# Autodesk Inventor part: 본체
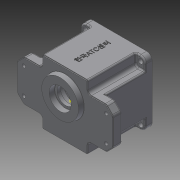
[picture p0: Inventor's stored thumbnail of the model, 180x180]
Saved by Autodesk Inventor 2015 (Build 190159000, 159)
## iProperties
Created: 2016-02
Part Number: 본체
Material: Generic
Document SubType Name: Modeling
Designer: Administrator
Density: 1 g/cm^3
Appearance: Default
Author: Administrator
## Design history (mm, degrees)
sketch "Sketch1"
  geometry: L1 (47, -47)-(-47, -47); L2 (-47, -47)-(-47, 47); L3 (-47, 47)-(47, 47); L4 (47, 47)-(47, -47); L5 (47, -47)-(-47, 47); L6 (-47, -47)-(47, 47); 1 further point
  constraints: 12 end point, 2 midpoint, 2 parallel, 1 horizontal, 1 perpendicular
  dimensions: "d0" = 94 distance of L2.end L3.end; "d1" = 94 distance of L1.end L2.end
extrude "Extrusion1" new body sketch "Sketch1" distance "d2" = 10; taper "d3" = 0 deg
workplane "Work Plane1"
sketch "Sketch2"
  geometry: L1 (33, -47)-(-33, -47); L2 (-33, 47)-(33, 47); L3 (33, -47)-(-33, 47); L4 (-33, -47)-(33, 47); L5 (-70, 30)-(-70, -30); L6 (70, -30)-(70, 30); L7 (70, 30)-(33, 30); L8 (-33, 30)-(-70, 30); L9 (-70, -30)-(-33, -30); L10 (33, -30)-(70, -30); L11 (33, 47)-(33, 30); L12 (33, -30)-(33, -47); L13 (-33, -47)-(-33, -30); L14 (-33, 30)-(-33, 47); 1 further point
  constraints: 28 end point, 10 parallel, 4 perpendicular, 3 horizontal, 2 midpoint
  dimensions: "d5" = 94 distance of L1.end L2.start; "d6" = 66 distance of L2.start L2.end; "d8" = 140 distance of L6.end L5.start; "d9" = 70 distance from line of L5 point (0, 0); "d10" = 60 distance of L5.start L5.end
extrude "Extrusion2" join sketch "Sketch2" distance "d12" = 13; taper "d13" = 0 deg
workplane "Work Plane2"
sketch "Sketch3"
  geometry: L1 (47, -47)-(-47, -47) reference; L2 (-47, -47)-(-47, 47) reference; L3 (-47, 47)-(47, 47) reference; L4 (47, 47)-(47, -47) reference; L5 (-33, 30)-(-33, 47) reference; L6 (-47, 47)-(-33, 47); L7 (-33, 47)-(-33, 30); L8 (-33, 30)-(-47, 30); L9 (-47, 30)-(-47, 47); L10 (-47, -47)-(-33, -47); L11 (-33, -47)-(-33, -30); L12 (-33, -30)-(-47, -30); L13 (-47, -30)-(-47, -47); L14 (47, -47)-(33, -47); L15 (33, -47)-(33, -30); L16 (33, -30)-(47, -30); L17 (47, -30)-(47, -47); L18 (47, 47)-(33, 47); L19 (33, 47)-(33, 30); L20 (33, 30)-(47, 30); L21 (47, 30)-(47, 47); 1 further point
  constraints: 32 end point, 8 parallel, 4 horizontal, 4 perpendicular
extrude "Extrusion3" join sketch "Sketch3" stored distance "d15" = 10; taper "d16" = 0 deg
sketch "Sketch4"
  geometry: L1 (47, 47)-(33, 47); L2 (33, 47)-(33, 30); L3 (33, 30)-(47, 30); L4 (47, 30)-(47, 47); L5 (47, -47)-(33, -47); L6 (33, -47)-(33, -30); L7 (33, -30)-(47, -30); L8 (47, -30)-(47, -47); L9 (-47, -47)-(-33, -47); L10 (-33, -47)-(-33, -30); L11 (-33, -30)-(-47, -30); L12 (-47, -30)-(-47, -47); L13 (-47, 47)-(-33, 47); L14 (-33, 47)-(-33, 30); L15 (-33, 30)-(-47, 30); L16 (-47, 30)-(-47, 47); 1 further point
  constraints: 32 end point, 8 parallel, 4 horizontal, 4 perpendicular
extrude "Extrusion4" cut sketch "Sketch4" distance "d17" = 60; taper "d18" = 0 deg
fillet "Fillet1" dims "d19" = 8
sketch "Sketch5"
  geometry: C1 r 43 at (0, 0); 1 further point
  constraints: 1 centre point, 1 coincident
  dimensions: "d20" = 43 radius of C1
extrude "Extrusion5" cut sketch "Sketch5" distance "d21" = 9; taper "d22" = 0 deg
sketch "Sketch6"
  geometry: A1 r 40 centre (0, 0) between (40, 0) and (39.148, 8.214); A2 r 36 centre (0, 0) between (36, 0) and (-36, 0); A3 r 4 centre (36, 0) between (35.852, 3.997) and (35.852, -3.997); A4 r 4 centre (-36, 0) between (-35.852, -3.997) and (-35.852, 3.997); A5 r 3.5 centre (35.722, -7.495) between (39.148, -8.214) and (35.778, -3.995); A6 r 3.5 centre (35.722, 7.495) between (35.778, 3.995) and (39.148, 8.214); A7 r 3.5 centre (-35.722, -7.495) between (-35.778, -3.995) and (-39.148, -8.214); A8 r 3.5 centre (-35.722, 7.495) between (-39.148, 8.214) and (-35.778, 3.995); A9 r 40 centre (0, 0) between (39.148, -8.214) and (40, 0); A10 r 40 centre (0, 0) between (39.148, 8.214) and (-39.148, 8.214); A11 r 4 centre (36, 0) between (40, 0) and (35.852, 3.997); A12 r 4 centre (36, 0) between (35.852, -3.997) and (40, 0); A13 r 4 centre (-36, 0) between (-40, 0) and (-35.852, -3.997); A14 r 4 centre (-36, 0) between (-35.852, 3.997) and (-40, 0); A15 r 40 centre (0, 0) between (-39.148, 8.214) and (-39.148, -8.214); A16 r 40 centre (0, 0) between (-39.148, -8.214) and (39.148, -8.214); 1 further point
  constraints: 46 point on circle, 16 centre point, 8 tangent, 2 coincident, 2 horizontal alignment
  dimensions: "d81" = 40 radius of A1; "d160" = 72 diameter of A2; "d161" = 4 radius of A3; "d162" = 4 radius of A4; "d163" = 3.5 radius of A7; "d164" = 3.5 radius of A8; "d165" = 3.5 radius of A5; "d166" = 3.5 radius of A6
extrude "Extrusion6" cut sketch "Sketch6" distance "d24" = 62; taper "d25" = 0 deg
sketch "Sketch8"
  geometry: C1 r 28 at (0, 11); 1 further point
  constraints: 1 centre point, 1 vertical alignment
  dimensions: "d32" = 28 radius of C1; "d33" = 11 distance of point (0, 0) C1.centre
extrude "Extrusion8" join sketch "Sketch8" distance "d34" = 7; taper "d35" = -10 deg
sketch "Sketch9"
  geometry: 1 further point
sketch "Sketch10"
  geometry: C1 r 21 at (0, -11); 1 further point
  constraints: 1 centre point, 1 vertical alignment
  dimensions: "d36" = 21 radius of C1; "d37" = 11 distance of point (0, 0) C1.centre
extrude "Extrusion9" join sketch "Sketch10" distance "d38" = 7; taper "d39" = 0 deg
sketch "Sketch12"
  geometry: C1 r 16 at (0, 0); C2 r 28 at (0, 0) reference; 1 further point
  constraints: 1 centre point, 1 concentric
  dimensions: "d43" = 16 radius of C1
extrude "Extrusion11" cut sketch "Sketch12" distance "d44" = 8; taper "d45" = 0 deg
sketch "Sketch13"
  geometry: C1 r 15 at (0, 20); 1 further point
  constraints: 1 centre point, 1 vertical alignment
  dimensions: "d46" = 15 radius of C1; "d47" = 20 distance of point (0, 0) C1.centre
extrude "Extrusion12" join sketch "Sketch13" distance "d48" = 7; taper "d49" = 0 deg
sketch "Sketch14"
  geometry: C1 r 11 at (0, 20); A1 r 15 centre (0, 20) between (8.978, 7.984) and (-8.978, 7.984) reference; 1 further point
  constraints: 1 centre point, 1 coincident, 1 vertical alignment
  dimensions: "d50" = 11 radius of C1
extrude "Extrusion13" cut sketch "Sketch14" distance "d51" = 7; taper "d52" = 0 deg
sketch "Sketch15"
  geometry: C1 r 9.5 at (0, 0); C2 r 11 at (0, 0) reference; 1 further point
  constraints: 1 centre point, 1 concentric
  dimensions: "d53" = 9.5 radius of C1
extrude "Extrusion14" cut sketch "Sketch15" distance "d54" = 1; taper "d55" = 0 deg
chamfer "Chamfer1" distance "d56" = 10; stored, may be unused: second distance "d57" = 2, angle "d58" = 45 deg
fillet "Fillet2" dims "d62" = 2
fillet "Fillet4" dims "d64" = 2
fillet "Fillet5" dims "d65" = 3
sketch "Sketch18"
  geometry: L1 (40, 40)-(-40, 40); L2 (-40, 40)-(-40, -40); L3 (-40, -40)-(40, -40); L4 (40, -40)-(40, 40); L5 (40, 40)-(-40, -40); L6 (-40, 40)-(40, -40); 5 further points
  constraints: 12 end point, 4 coincident, 2 midpoint, 2 parallel, 1 horizontal, 1 perpendicular
  dimensions: "d91" = 80 distance of L3.end L2.end; "d92" = 80 distance of L2.end L1.end
hole "Hole1" sketch "Sketch18" at (40, -40), (-40, -40), (-40, 40), (40, 40) diameter "d93" = 7; stored, may be unused: countersink angle "d97" = 90 deg, drill point angle "d99" = 118 deg; dims "d94" = 6, "d95" = 4, "d96" = 2, "d98" = 8
fillet "Fillet7" dims "d100" = 3
sketch "Sketch19"
  geometry: L1 (-60, -19)-(60, -19); L2 (60, -19)-(60, 19); L3 (60, 19)-(-60, 19); L4 (-60, 19)-(-60, -19); L5 (-60, -19)-(60, 19); L6 (60, -19)-(-60, 19); 5 further points
  constraints: 12 end point, 4 coincident, 2 midpoint, 2 parallel, 1 horizontal, 1 perpendicular
  dimensions: "d101" = 120 distance of L3.end L2.end; "d102" = 38 distance of L2.end L1.end
sketch "Sketch20"
  geometry: L1 (-60, 19)-(60, 19) reference; L2 (-60, -19)-(-60, 19) reference; L3 (60, -19)-(-60, -19) reference; L4 (60, 19)-(60, -19) reference; 5 further points
  constraints: 4 coincident
hole "Hole2" sketch "Sketch20" at (-60, 19), (60, 19), (60, -19), (-60, -19) diameter "d103" = 5; stored, may be unused: countersink angle "d107" = 90 deg, drill point angle "d109" = 118 deg; dims "d104" = 6, "d105" = 9, "d106" = 4, "d108" = 8
chamfer "Chamfer3" distance "d115" = 1; stored, may be unused: second distance "d116" = 2, angle "d117" = 45 deg
fillet "Fillet8" dims "d121" = 0.3
fillet "Fillet9" dims "d122" = 1
sketch "Sketch25"
  geometry: L1 (0, 0)-(78, 0) reference; L2 (39, 16)-(39, -96) reference; 2 further points
  constraints: 1 midpoint, 1 other
  dimensions: "d123" = 40 distance from line of L1 point (39, -40)
emboss "Emboss1" sketch "Sketch25" dims "d124" = 0.5, "d125" = 0
fillet "Fillet12" dims "d128" = 5
fillet "Fillet13" dims "d129" = 5
fillet "Fillet14" dims "d130" = 2
fillet "Fillet15" dims "d131" = 2
sketch "Sketch26"
  geometry: C1 r 17.5 at (0, -11); A1 r 21 centre (0, -11) between (-12.163, 6.119) and (12.163, 6.119) reference; 1 further point
  constraints: 1 centre point, 1 concentric
  dimensions: "d132" = 17.5 radius of C1
extrude "Extrusion20" cut sketch "Sketch26" distance "d133" = 10; taper "d134" = 0 deg
sketch "Sketch27"
  geometry: C1 r 12.5 at (0, 0); C2 r 17.5 at (0, 0) reference; 1 further point
  constraints: 1 centre point, 1 concentric
  dimensions: "d135" = 12.5 radius of C1
extrude "Extrusion21" cut sketch "Sketch27" distance "d136" = 5; taper "d137" = 0 deg
fillet "Fillet16" dims "d138" = 0.3
chamfer "Chamfer4" distance "d139" = 1; stored, may be unused: second distance "d140" = 2, angle "d141" = 45 deg
fillet "Fillet19" dims "d145" = 2
sketch "Sketch30"
  geometry: L1 (-33, 45)-(-33, 35) reference; L2 (-38, 30)-(-57.929, 30) reference; L3 (-68.536, 21.464)-(-61.464, 28.536) reference; L4 (-70, 17.929)-(-70, -17.929) reference; L5 (-61.464, -28.536)-(-68.536, -21.464) reference; L6 (-57.929, -30)-(-38, -30) reference; L7 (-33, -35)-(-33, -45) reference; L8 (-31, -47)-(31, -47) reference; L9 (33, -45)-(33, -35) reference; L10 (38, -30)-(57.929, -30) reference; L11 (68.536, -21.464)-(61.464, -28.536) reference; L12 (70, -17.929)-(70, 17.929) reference; L13 (61.464, 28.536)-(68.536, 21.464) reference; L14 (57.929, 30)-(38, 30) reference; L15 (33, 35)-(33, 45) reference; L16 (31, 47)-(-31, 47) reference; L17 (-32, 45)-(-32, 35); L18 (-38, 29)-(-57.929, 29); L19 (-60.757, 27.828)-(-67.828, 20.757); L20 (-69, 17.929)-(-69, -17.929); L21 (-67.828, -20.757)-(-60.757, -27.828); L22 (-57.929, -29)-(-38, -29); L23 (-32, -35)-(-32, -45); L24 (-31, -46)-(31, -46); L25 (32, -45)-(32, -35); L26 (38, -29)-(57.929, -29); L27 (60.757, -27.828)-(67.828, -20.757); L28 (69, -17.929)-(69, 17.929); L29 (67.828, 20.757)-(60.757, 27.828); L30 (57.929, 29)-(38, 29); L31 (32, 35)-(32, 45); L32 (31, 46)-(-31, 46); C1 r 2.5 at (60, 19) reference; C2 r 2.5 at (-60, -19) reference; C3 r 2.5 at (60, -19) reference; C4 r 2.5 at (-60, 19) reference; C5 r 28 at (0, 11) reference; A1 r 2 centre (-31, 45) between (-31, 47) and (-33, 45) reference; A2 r 5 centre (-38, 35) between (-38, 30) and (-33, 35) reference; A3 r 5 centre (-57.929, 25) between (-57.929, 30) and (-61.464, 28.536) reference; A4 r 5 centre (-65, 17.929) between (-68.536, 21.464) and (-70, 17.929) reference; A5 r 5 centre (-65, -17.929) between (-70, -17.929) and (-68.536, -21.464) reference; A6 r 5 centre (-57.929, -25) between (-61.464, -28.536) and (-57.929, -30) reference; A7 r 5 centre (-38, -35) between (-33, -35) and (-38, -30) reference; A8 r 2 centre (-31, -45) between (-33, -45) and (-31, -47) reference; A9 r 2 centre (31, -45) between (31, -47) and (33, -45) reference; A10 r 5 centre (38, -35) between (38, -30) and (33, -35) reference; A11 r 5 centre (57.929, -25) between (57.929, -30) and (61.464, -28.536) reference; A12 r 5 centre (65, -17.929) between (68.536, -21.464) and (70, -17.929) reference; A13 r 5 centre (65, 17.929) between (70, 17.929) and (68.536, 21.464) reference; A14 r 5 centre (57.929, 25) between (61.464, 28.536) and (57.929, 30) reference; A15 r 5 centre (38, 35) between (33, 35) and (38, 30) reference; A16 r 2 centre (31, 45) between (33, 45) and (31, 47) reference; A17 r 1 centre (-31, 45) between (-31, 46) and (-32, 45); A18 r 6 centre (-38, 35) between (-38, 29) and (-32, 35); A19 r 4 centre (-57.929, 25) between (-57.929, 29) and (-60.757, 27.828); A20 r 4 centre (-65, 17.929) between (-67.828, 20.757) and (-69, 17.929); A21 r 4 centre (-65, -17.929) between (-69, -17.929) and (-67.828, -20.757); A22 r 4 centre (-57.929, -25) between (-60.757, -27.828) and (-57.929, -29); A23 r 6 centre (-38, -35) between (-32, -35) and (-38, -29); A24 r 1 centre (-31, -45) between (-32, -45) and (-31, -46); A25 r 1 centre (31, -45) between (31, -46) and (32, -45); A26 r 6 centre (38, -35) between (38, -29) and (32, -35); A27 r 4 centre (57.929, -25) between (57.929, -29) and (60.757, -27.828); A28 r 4 centre (65, -17.929) between (67.828, -20.757) and (69, -17.929); A29 r 4 centre (65, 17.929) between (69, 17.929) and (67.828, 20.757); A30 r 4 centre (57.929, 25) between (60.757, 27.828) and (57.929, 29); A31 r 6 centre (38, 35) between (32, 35) and (38, 29); A32 r 1 centre (31, 45) between (32, 45) and (31, 46); 1 further point
  constraints: 32 end point, 32 point on circle, 16 centre point, 31 other
  dimensions: "d146" = 1 distance between parallel lines of L16 L32
extrude "Extrusion22" cut sketch "Sketch30" distance "d147" = 1; taper "d148" = 0 deg
fillet "Fillet20" dims "d167" = 2
sketch "Sketch32"
  geometry: A1 r 4 centre (36, 0) between (35.852, 3.997) and (35.852, -3.997) reference; A2 r 4 centre (-36, 0) between (-35.852, -3.997) and (-35.852, 3.997) reference; 3 further points
  constraints: 2 coincident
hole "Hole4" sketch "Sketch32" at (36, 0), (-36, 0) diameter "d168" = 3.242; stored, may be unused: countersink angle "d172" = 90 deg, drill point angle "d174" = 118 deg; dims "d169" = 7, "d170" = 4, "d171" = 2, "d173" = 9
fillet "Fillet21" dims "d175" = 0.3
body "Solid1"
node "Projected Loop1"
node "Projected Loop4"
other parameters: "d82" = 4, "d83" = 4
